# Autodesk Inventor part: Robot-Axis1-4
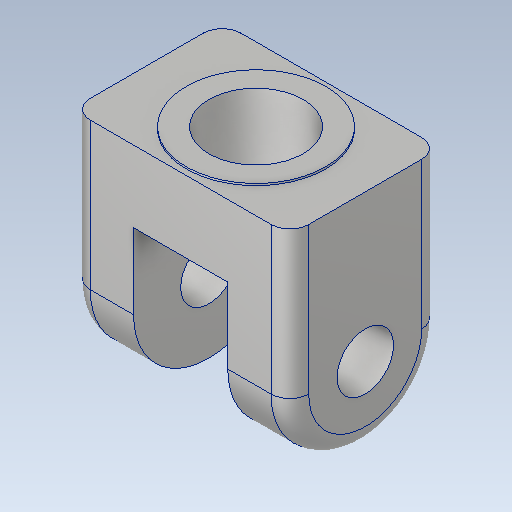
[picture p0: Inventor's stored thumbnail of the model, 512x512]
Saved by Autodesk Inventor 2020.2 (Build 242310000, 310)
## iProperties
Created: 2018-07
Part Number: Robot-Axis1-4
Material: Aluminum 6061
Description: 123456
Document SubType Name: Modeling
Designer: Power User
Mass: 1617.3 g
Surface Area: 678.793 cm^2
Volume: 599 cm^3
Density: 2.7 g/cm^3
Appearance: Aluminum - Flat
Title: GEAR
Author: Power User
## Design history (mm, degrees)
sketch "Sketch6" dims "d45" = 80
  geometry: L1 (0, 40)-(78, 40); L2 (78, 40)-(78, -40); L3 (78, -40)-(0, -40); L4 (0, -40)-(0, 40); 3 further points
  constraints: 8 end point, 3 horizontal, 2 parallel, 1 coincident, 1 midpoint, 1 perpendicular, 1 vertical alignment, 2 other
  dimensions: "d46" = 78 distance of L2.end L3.end
extrude "Extrusion5" new body sketch "Sketch6" stored distance "d47" = 116; taper "d48" = 0 deg
sketch "Sketch7"
  geometry: A1 r 40 centre (0, 0) between (-40, 0) and (40, 0) reference; 2 further points
  constraints: 1 coincident
hole "Hole2" sketch "Sketch7" at (0, 0) diameter "d49" = 30; stored, may be unused: countersink angle "d53" = 90 deg, drill point angle "d55" = 118 deg; dims "d50" = 6, "d51" = 4, "d52" = 2, "d54" = 8
sketch "Sketch8"
  geometry: L1 (-25, 40)-(25, 40); L2 (25, 40)-(25, -45.089); L3 (25, -45.089)-(-25, -45.089); L4 (-25, -45.089)-(-25, 40); L5 (58, 15)-(-58, 15) reference; L6 (-58, 15)-(-58, 78) reference; L7 (-58, 78)-(58, 78) reference; L8 (58, 78)-(58, 15) reference; L9 (-58, -15)-(58, -15) reference; L10 (58, -15)-(58, -40) reference; L11 (58, -40)-(-58, -40) reference; L12 (-58, -40)-(-58, -15) reference; 2 further points
  constraints: 8 end point, 2 parallel, 1 horizontal, 1 midpoint, 1 perpendicular, 1 vertical alignment
  dimensions: "d56" = 50 distance of L2.end L3.end; "d57" = 80 distance between parallel lines of L11 L1
extrude "Extrusion6" cut sketch "Sketch8" extent not by distance; stored distance "d58" = 116; taper "d59" = 0 deg
sketch "Sketch9"
  geometry: C1 r 37 at (58, 40); 1 further point
  constraints: 1 centre point, 1 coincident
  dimensions: "d64" = 74 diameter of C1
extrude "Extrusion7" join sketch "Sketch9" distance "d62" = 1; taper "d63" = 0 deg
sketch "Sketch10"
  geometry: C1 r 37 at (0, 0) reference; 2 further points
  constraints: 1 coincident
hole "Hole3" sketch "Sketch10" at (0, 0) diameter "d65" = 50; stored, may be unused: countersink angle "d69" = 90 deg, drill point angle "d71" = 118 deg; dims "d66" = 6, "d67" = 4, "d68" = 2, "d70" = 8
fillet "Fillet2" dims "d72" = 10
body "Solid2"
node "Project Cut Edges2"
